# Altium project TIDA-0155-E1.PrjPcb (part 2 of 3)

## Sheet Page3.SchDoc
size 431 x 279 mm; Date: Not shown in title block; ApprovedBy: Not shown in title block; CheckedBy: Not shown in title block; Author: Not shown in title block; CompanyName: Not shown in title block; Engineer: Not shown in title block; Organization: Not shown in title block; Address1: Not shown in title block; Address2: Not shown in title block; Address3: Not shown in title block; Address4: Not shown in title block; DocumentNumber: 1; Revision: Use project parameter SCH_Rev; SheetNumber: 2; SheetTotal: 3; PageSetup: Record=PageOptions¦CenterHorizontal=True¦CenterVertical=True¦PrintScale=1.00¦XCorrection=1.00¦YCorrection=1.00¦PrintKind=0¦BorderSize=5000000¦LeftOffset=0¦BottomOffset=0¦Orientation=2¦PaperLength=1000¦PaperWidth=1000¦Scale=100¦PaperSource=15¦PrintQuality=600¦MediaType=1¦DitherType=10¦PaperKind=Letter¦PrintScaleMode=1
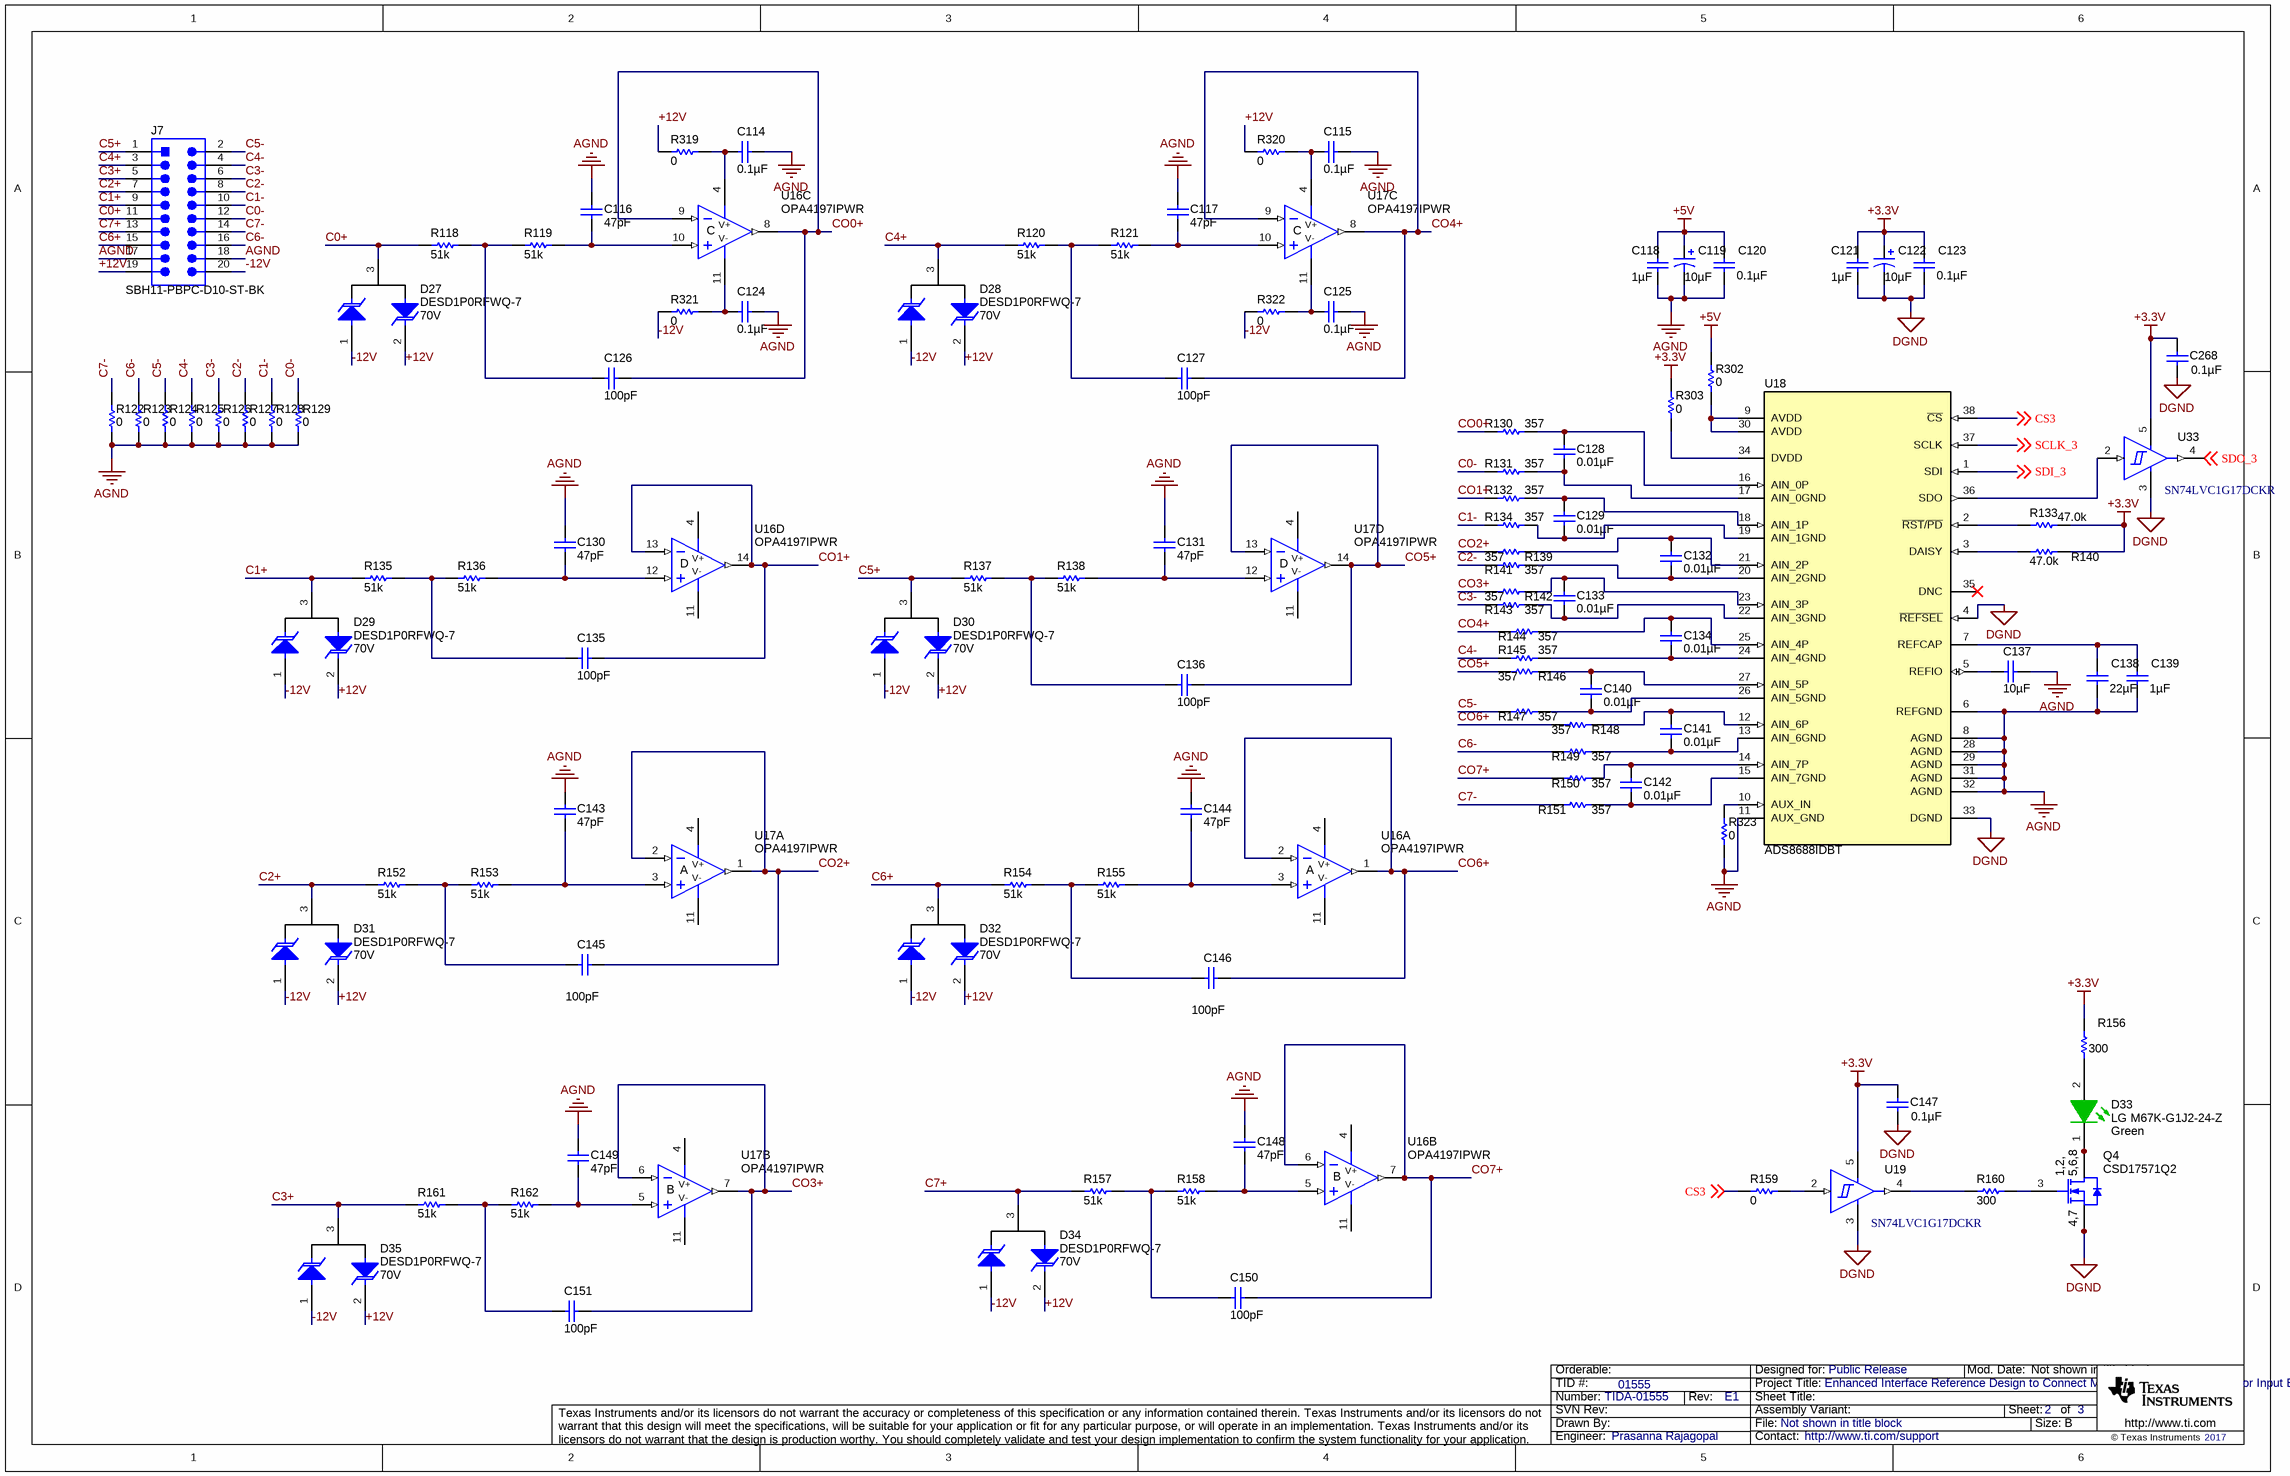
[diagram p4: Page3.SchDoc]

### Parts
C114  ValueDisplayed: 0.1µF  [0603]  (hidden comment: 06035C104KAT2A)
C115  ValueDisplayed: 0.1µF  [0603]  (hidden comment: 06035C104KAT2A)
C116  ValueDisplayed: 47pF  [0603]  (hidden comment: C0603C470J5GACTU)
C117  ValueDisplayed: 47pF  [0603]  (hidden comment: C0603C470J5GACTU)
C118  ValueDisplayed: 1µF  [0805_HV]  (hidden comment: LMK212B7105KD-T)
C119  ValueDisplayed: 10µF  [3216-18]  (hidden comment: TAJA106M010RNJ)
C120  ValueDisplayed: 0.1µF  [0402]  (hidden comment: C1005X5R1A104K050BA)
C121  ValueDisplayed: 1µF  [0805_HV]  (hidden comment: LMK212B7105KD-T)
C122  ValueDisplayed: 10µF  [3216-18]  (hidden comment: TAJA106M010RNJ)
C123  ValueDisplayed: 0.1µF  [0402]  (hidden comment: C1005X5R1A104K050BA)
C124  ValueDisplayed: 0.1µF  [0603]  (hidden comment: 06035C104KAT2A)
C125  ValueDisplayed: 0.1µF  [0603]  (hidden comment: 06035C104KAT2A)
C126  ValueDisplayed: 100pF  [0603]  (hidden comment: 06035A101FAT2A)
C127  ValueDisplayed: 100pF  [0603]  (hidden comment: 06035A101FAT2A)
C128  ValueDisplayed: 0.01µF  [0603]  (hidden comment: C1608X7R1H103K080AA)
C129  ValueDisplayed: 0.01µF  [0603]  (hidden comment: C1608X7R1H103K080AA)
C130  ValueDisplayed: 47pF  [0603]  (hidden comment: C0603C470J5GACTU)
C131  ValueDisplayed: 47pF  [0603]  (hidden comment: C0603C470J5GACTU)
C132  ValueDisplayed: 0.01µF  [0603]  (hidden comment: C1608X7R1H103K080AA)
C133  ValueDisplayed: 0.01µF  [0603]  (hidden comment: C1608X7R1H103K080AA)
C134  ValueDisplayed: 0.01µF  [0603]  (hidden comment: C1608X7R1H103K080AA)
C135  ValueDisplayed: 100pF  [0603]  (hidden comment: 06035A101FAT2A)
C136  ValueDisplayed: 100pF  [0603]  (hidden comment: 06035A101FAT2A)
C137  ValueDisplayed: 10µF  [0805_HV]  (hidden comment: GRM21BR71A106KE51L)
C138  ValueDisplayed: 22µF  [1210_280]  (hidden comment: C3225X7R1C226K250AC)
C139  ValueDisplayed: 1µF  [0603]  (hidden comment: C1608X7R1C105K080AC)
C140  ValueDisplayed: 0.01µF  [0603]  (hidden comment: C1608X7R1H103K080AA)
C141  ValueDisplayed: 0.01µF  [0603]  (hidden comment: C1608X7R1H103K080AA)
C142  ValueDisplayed: 0.01µF  [0603]  (hidden comment: C1608X7R1H103K080AA)
C143  ValueDisplayed: 47pF  [0603]  (hidden comment: C0603C470J5GACTU)
C144  ValueDisplayed: 47pF  [0603]  (hidden comment: C0603C470J5GACTU)
C145  ValueDisplayed: 100pF  [0603]  (hidden comment: 06035A101FAT2A)
C146  ValueDisplayed: 100pF  [0603]  (hidden comment: 06035A101FAT2A)
C147  ValueDisplayed: 0.1µF  [0603]  (hidden comment: GRM188R71C104KA01D)
C148  ValueDisplayed: 47pF  [0603]  (hidden comment: C0603C470J5GACTU)
C149  ValueDisplayed: 47pF  [0603]  (hidden comment: C0603C470J5GACTU)
C150  ValueDisplayed: 100pF  [0603]  (hidden comment: 06035A101FAT2A)
C151  ValueDisplayed: 100pF  [0603]  (hidden comment: 06035A101FAT2A)
C268  ValueDisplayed: 0.1µF  [0603]  (hidden comment: GRM188R71C104KA01D)
D27  DESD1P0RFWQ-7  value 70V  [SOT-323]
D28  DESD1P0RFWQ-7  value 70V  [SOT-323]
D29  DESD1P0RFWQ-7  value 70V  [SOT-323]
D30  DESD1P0RFWQ-7  value 70V  [SOT-323]
D31  DESD1P0RFWQ-7  value 70V  [SOT-323]
D32  DESD1P0RFWQ-7  value 70V  [SOT-323]
D33  LG M67K-G1J2-24-Z  value Green  [LG_M67K_Green]
D34  DESD1P0RFWQ-7  value 70V  [SOT-323]
D35  DESD1P0RFWQ-7  value 70V  [SOT-323]
J7  SBH11-PBPC-D10-ST-BK  [Sullins_SBH11-xxxC-D10-ST]
Q4  CSD17571Q2  [DQK0006C]
R118  ValueDisplayed: 51k  [0603]  (hidden comment: CRCW060351K0JNEA)
R119  ValueDisplayed: 51k  [0603]  (hidden comment: CRCW060351K0JNEA)
R120  ValueDisplayed: 51k  [0603]  (hidden comment: CRCW060351K0JNEA)
R121  ValueDisplayed: 51k  [0603]  (hidden comment: CRCW060351K0JNEA)
R122  ValueDisplayed: 0  [0603]  (hidden comment: CRCW06030000Z0EA)
R123  ValueDisplayed: 0  [0603]  (hidden comment: CRCW06030000Z0EA)
R124  ValueDisplayed: 0  [0603]  (hidden comment: CRCW06030000Z0EA)
R125  ValueDisplayed: 0  [0603]  (hidden comment: CRCW06030000Z0EA)
R126  ValueDisplayed: 0  [0603]  (hidden comment: CRCW06030000Z0EA)
R127  ValueDisplayed: 0  [0603]  (hidden comment: CRCW06030000Z0EA)
R128  ValueDisplayed: 0  [0603]  (hidden comment: CRCW06030000Z0EA)
R129  ValueDisplayed: 0  [0603]  (hidden comment: CRCW06030000Z0EA)
R130  ValueDisplayed: 357  [0402]  (hidden comment: CRCW0402357RFKED)
R131  ValueDisplayed: 357  [0402]  (hidden comment: CRCW0402357RFKED)
R132  ValueDisplayed: 357  [0402]  (hidden comment: CRCW0402357RFKED)
R133  ValueDisplayed: 47.0k  [0603]  (hidden comment: RC0603FR-0747KL)
R134  ValueDisplayed: 357  [0402]  (hidden comment: CRCW0402357RFKED)
R135  ValueDisplayed: 51k  [0603]  (hidden comment: CRCW060351K0JNEA)
R136  ValueDisplayed: 51k  [0603]  (hidden comment: CRCW060351K0JNEA)
R137  ValueDisplayed: 51k  [0603]  (hidden comment: CRCW060351K0JNEA)
R138  ValueDisplayed: 51k  [0603]  (hidden comment: CRCW060351K0JNEA)
R139  ValueDisplayed: 357  [0402]  (hidden comment: CRCW0402357RFKED)
R140  ValueDisplayed: 47.0k  [0603]  (hidden comment: RC0603FR-0747KL)
R141  ValueDisplayed: 357  [0402]  (hidden comment: CRCW0402357RFKED)
R142  ValueDisplayed: 357  [0402]  (hidden comment: CRCW0402357RFKED)
R143  ValueDisplayed: 357  [0402]  (hidden comment: CRCW0402357RFKED)
R144  ValueDisplayed: 357  [0402]  (hidden comment: CRCW0402357RFKED)
R145  ValueDisplayed: 357  [0402]  (hidden comment: CRCW0402357RFKED)
R146  ValueDisplayed: 357  [0402]  (hidden comment: CRCW0402357RFKED)
R147  ValueDisplayed: 357  [0402]  (hidden comment: CRCW0402357RFKED)
R148  ValueDisplayed: 357  [0402]  (hidden comment: CRCW0402357RFKED)
R149  ValueDisplayed: 357  [0402]  (hidden comment: CRCW0402357RFKED)
R150  ValueDisplayed: 357  [0402]  (hidden comment: CRCW0402357RFKED)
R151  ValueDisplayed: 357  [0402]  (hidden comment: CRCW0402357RFKED)
R152  ValueDisplayed: 51k  [0603]  (hidden comment: CRCW060351K0JNEA)
R153  ValueDisplayed: 51k  [0603]  (hidden comment: CRCW060351K0JNEA)
R154  ValueDisplayed: 51k  [0603]  (hidden comment: CRCW060351K0JNEA)
R155  ValueDisplayed: 51k  [0603]  (hidden comment: CRCW060351K0JNEA)
R156  ValueDisplayed: 300  [0603]  (hidden comment: CRCW0603300RJNEA)
R157  ValueDisplayed: 51k  [0603]  (hidden comment: CRCW060351K0JNEA)
R158  ValueDisplayed: 51k  [0603]  (hidden comment: CRCW060351K0JNEA)
R159  ValueDisplayed: 0  [0603]  (hidden comment: RMCF0603ZT0R00)
R160  ValueDisplayed: 300  [0603]  (hidden comment: CRCW0603300RJNEA)
R161  ValueDisplayed: 51k  [0603]  (hidden comment: CRCW060351K0JNEA)
R162  ValueDisplayed: 51k  [0603]  (hidden comment: CRCW060351K0JNEA)
R302  ValueDisplayed: 0  [0603]  (hidden comment: CRCW06030000Z0EA)
R303  ValueDisplayed: 0  [0603]  (hidden comment: CRCW06030000Z0EA)
R319  ValueDisplayed: 0  [0402]  (hidden comment: CRCW04020000Z0ED)
R320  ValueDisplayed: 0  [0402]  (hidden comment: CRCW04020000Z0ED)
R321  ValueDisplayed: 0  [0402]  (hidden comment: CRCW04020000Z0ED)
R322  ValueDisplayed: 0  [0402]  (hidden comment: CRCW04020000Z0ED)
R323  ValueDisplayed: 0  [0402]  (hidden comment: CRCW04020000Z0ED)
U16  OPA4197IPWR  [PW0014A_N]  (parts A,B,C,D of 4)
U17  OPA4197IPWR  [PW0014A_N]  (parts A,B,C,D of 4)
U18  ADS8688IDBT  [DBT0038A_N]
U19  SN74LVC1G17DCKR  [DCK0005A_N]
U33  SN74LVC1G17DCKR  [DCK0005A_N]

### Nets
+3.3V: C121.1 C122.1(+) C123.1 C147.1 C268.1 R133.2 R140.2 R156.2 R303.2 U19.5(VCC) U33.5(VCC)
+5V: C118.1 C119.1(+) C120.1 R302.2
+12V: D27.2(C) D28.2(C) D29.2(C) D30.2(C) D31.2(C) D32.2(C) D34.2(C) D35.2(C) J7.19 R319.1 R320.1
-12V: D27.1(A) D28.1(A) D29.1(A) D30.1(A) D31.1(A) D32.1(A) D34.1(A) D35.1(A) J7.20 R321.1 R322.1
AGND: C114.1 C115.1 C116.1 C117.1 C118.2 C119.2(-) C120.2 C124.1 C125.1 C130.1 C131.1 C137.2 C138.2 C139.2 C143.1 C144.1 C148.1 C149.1 J7.17 J7.18 R122.1 R123.1 R124.1 R125.1 R126.1 R127.1 R128.1 R129.1 R323.1 U18.6(REFGND) U18.8(AGND) U18.11(AUX_GND) U18.28(AGND) U18.29(AGND) U18.31(AGND) U18.32(AGND)
DGND: C121.2 C122.2(-) C123.2 C147.2 C268.2 Q4.4(S) Q4.7(S) U18.4(~{REFSEL}) U18.33(DGND) U19.3(GND) U33.3(GND)
C0+: D27.3(C) J7.11 R118.1
C0-: J7.12 R129.2 R131.1
C1+: D29.3(C) J7.9 R135.1
C1-: J7.10 R128.2 R134.1
C2+: D31.3(C) J7.7 R152.1
C2-: J7.8 R127.2 R141.1
C3+: D35.3(C) J7.5 R161.1
C3-: J7.6 R126.2 R143.1
C4+: D28.3(C) J7.3 R120.1
C4-: J7.4 R125.2 R145.1
C5+: D30.3(C) J7.1 R137.1
C5-: J7.2 R124.2 R147.1
C6+: D32.3(C) J7.15 R154.1
C6-: J7.16 R123.2 R149.1
C7+: D34.3(C) J7.13 R157.1
C7-: J7.14 R122.2 R151.1
CO0+: C126.1 R130.1 U16.8(OUT) U16.9(IN-)
CO1+: C135.1 R132.1 U16.13(IN-) U16.14(OUT)
CO2+: C145.1 R139.1 U17.1(OUT) U17.2(IN-)
CO3+: C151.1 R142.1 U17.6(IN-) U17.7(OUT)
CO4+: C127.1 R144.1 U17.8(OUT) U17.9(IN-)
CO5+: C136.1 R146.1 U17.13(IN-) U17.14(OUT)
CO6+: C146.1 R148.1 U16.1(OUT) U16.2(IN-)
CO7+: C150.1 R150.1 U16.6(IN-) U16.7(OUT)
CS3: R159.1 U18.38(~{CS}) ; off-sheet CS3
SCLK_3: U18.37(SCLK) ; off-sheet SCLK_3
SDI_3: U18.1(SDI) ; off-sheet SDI_3
SDO_3: U33.4(Y) ; off-sheet SDO_3
NetC114_2: C114.2 R319.2 U16.4(V+)
NetC115_2: C115.2 R320.2 U17.4(V+)
NetC116_2: C116.2 R119.2 U16.10(IN+)
NetC117_2: C117.2 R121.2 U17.10(IN+)
NetC124_2: C124.2 R321.2 U16.11(V-)
NetC125_2: C125.2 R322.2 U17.11(V-)
NetC126_2: C126.2 R118.2 R119.1
NetC127_2: C127.2 R120.2 R121.1
NetC128_1: C128.1 R130.2 U18.16(AIN_0P)
NetC128_2: C128.2 R131.2 U18.17(AIN_0GND)
NetC129_1: C129.1 R132.2 U18.18(AIN_1P)
NetC129_2: C129.2 R134.2 U18.19(AIN_1GND)
NetC130_2: C130.2 R136.2 U16.12(IN+)
NetC131_2: C131.2 R138.2 U17.12(IN+)
NetC132_1: C132.1 R139.2 U18.21(AIN_2P)
NetC132_2: C132.2 R141.2 U18.20(AIN_2GND)
NetC133_1: C133.1 R142.2 U18.23(AIN_3P)
NetC133_2: C133.2 R143.2 U18.22(AIN_3GND)
NetC134_1: C134.1 R144.2 U18.25(AIN_4P)
NetC134_2: C134.2 R145.2 U18.24(AIN_4GND)
NetC135_2: C135.2 R135.2 R136.1
NetC136_2: C136.2 R137.2 R138.1
NetC137_1: C137.1 U18.5(REFIO)
NetC138_1: C138.1 C139.1 U18.7(REFCAP)
NetC140_1: C140.1 R146.2 U18.27(AIN_5P)
NetC140_2: C140.2 R147.2 U18.26(AIN_5GND)
NetC141_1: C141.1 R148.2 U18.12(AIN_6P)
NetC141_2: C141.2 R149.2 U18.13(AIN_6GND)
NetC142_1: C142.1 R150.2 U18.14(AIN_7P)
NetC142_2: C142.2 R151.2 U18.15(AIN_7GND)
NetC143_2: C143.2 R153.2 U17.3(IN+)
NetC144_2: C144.2 R155.2 U16.3(IN+)
NetC145_2: C145.2 R152.2 R153.1
NetC146_2: C146.2 R154.2 R155.1
NetC148_2: C148.2 R158.2 U16.5(IN+)
NetC149_2: C149.2 R162.2 U17.5(IN+)
NetC150_2: C150.2 R157.2 R158.1
NetC151_2: C151.2 R161.2 R162.1
NetD33_1: D33.1(K) Q4.1(D) Q4.2(D) Q4.5(D) Q4.6(D) Q4.8(D)
NetD33_2: D33.2(A) R156.1
NetQ4_3: Q4.3(G) R160.1
NetR133_1: R133.1 U18.2(~{RST}/~{PD})
NetR140_1: R140.1 U18.3(DAISY)
NetR159_2: R159.2 U19.2(A)
NetR160_2: R160.2 U19.4(Y)
NetR302_1: R302.1 U18.9(AVDD) U18.30(AVDD)
NetR303_1: R303.1 U18.34(DVDD)
NetR323_2: R323.2 U18.10(AUX_IN)
NetU18_36: U18.36(SDO) U33.2(A)

Not connected (* = marked no-connect by the designer): U18 35(DNC)*

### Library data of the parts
C114 C115 C124 C125 = 06035C104KAT2A: CAP, CERM, 0.1 µF, 50 V,+/- 10%, X7R, 0603; Manufacturer: AVX; Polarized: N; CompType: Capacitor; Value: 0.1uF; U/M: EA; Cap_F: 0.0000001; Tolerance_%: 10; VDC_V: 50; Value2: 50V; TaMin_C: -55; TaMax_C: 125; SizeArea_mm2: 1.28; SizeAreaWB_mm2: 4.68; SizeX_mm: 1.6; SizeY_mm: 0.8; SizeZ_mm: 1; AEC Category: Q200; Green_Lifecycle: Active; Green_REACh: Passed
C116 C117 C130 C131 C143 C144 C148 C149 = C0603C470J5GACTU: CAP, CERM, 47 pF, 50 V,+/- 5%, C0G/NP0, 0603; Manufacturer: Kemet; Polarized: N; CompType: Capacitor; Value: 47pF; U/M: EA; Cap_F: 0.000000000047; Tolerance_%: 5; VDC_V: 50; Value2: 50V; TaMin_C: -55; TaMax_C: 125; SizeArea_mm2: 1.28; SizeAreaWB_mm2: 4.68; SizeX_mm: 1.6; SizeY_mm: 0.8; SizeZ_mm: 1; AEC Category: Q200; Green_Lifecycle: Active; Green_REACh: Passed
C118 C121 = LMK212B7105KD-T: CAP, CERM, 1 µF, 10 V, +/- 10%, X7R, 0805; Manufacturer: Taiyo Yuden; Polarized: N; CompType: Capacitor; Value: 1uF; U/M: EA; Cap_F: 0.000001; Tolerance_%: 10; Value1: Unknown; Value2: 10V; TaMin_C: -55; TaMax_C: 125; Cap_Case: 0805; SizeArea_mm2: 2.5; SizeAreaWB_mm2: 6.75; SizeX_mm: 2; SizeY_mm: 1.25; SizeZ_mm: 1.45; AEC Category: Q200
C119 C122 = TAJA106M010RNJ: CAP, TA, 10 µF, 10 V, +/- 20%, 3 ohm, SMD; Manufacturer: AVX; Polarized: Y; CompType: Capacitor; Value: 10uF; U/M: EA; Cap_F: 0.00001; Tolerance_%: 20; Value1: 3 ohm; VDC_V: 10; Value2: 10V; ESR_ohm: 3; TaMin_C: -55; TaMax_C: 125; SizeAreaWB_mm2: 10.92; SizeArea_mm2: 5.12; SizeX_mm: 3.2; SizeY_mm: 1.6; SizeZ_mm: 1.8; AEC Category: Q200
C120 C123 = C1005X5R1A104K050BA: CAP, CERM, 0.1 µF, 10 V, +/- 10%, X5R, 0402; Manufacturer: TDK; Polarized: N; CompType: Capacitor; Value: 0.1uF; U/M: EA; Cap_F: 0.0000001; Tolerance_%: 10; Value1: Unknown; Value2: 10V; TaMin_C: -55; TaMax_C: 85; SizeArea_mm2: 0.5; SizeAreaWB_mm2: 3; SizeX_mm: 1; SizeZ_mm: 0.6; AEC Category: Q200
C126 C127 C135 C136 C145 C146 C150 C151 = 06035A101FAT2A: CAP, CERM, 100 pF, 50 V,+/- 1%, C0G/NP0, 0603; Manufacturer: AVX; Polarized: N; CompType: Capacitor; Value: 100pF; U/M: EA; Cap_F: 0.0000000001; Tolerance_%: 1; VDC_V: 50; Value2: 50V; TaMin_C: -55; TaMax_C: 125; SizeArea_mm2: 1.28; SizeAreaWB_mm2: 4.68; SizeX_mm: 1.6; SizeY_mm: 0.8; AEC Category: Q200; Green_Lifecycle: Active; Green_REACh: Passed
C128 C129 C132-C134 C140-C142 = C1608X7R1H103K080AA: CAP, CERM, 0.01 µF, 50 V,+/- 10%, X7R, 0603; Manufacturer: TDK; Polarized: N; CompType: Capacitor; Value: 0.01uF; U/M: EA; Cap_F: 0.00000001; Tolerance_%: 10; ESR_ohm: 0.0539; Value1: 0.0539 ohm; VDC_V: 50; Value2: 50V; TaMin_C: -55; TaMax_C: 125; SizeArea_mm2: 1.28; SizeAreaWB_mm2: 4.68; SizeX_mm: 1.6; SizeY_mm: 0.8; SizeZ_mm: 1; AEC Category: Q200; Green_Lifecycle: NRND; Green_REACh: Passed
C137 = GRM21BR71A106KE51L: CAP, CERM, 10 µF, 10 V,+/- 10%, X7R, 0805; Manufacturer: MuRata; Polarized: N; CompType: Capacitor; Value: 10uF; U/M: EA; Cap_F: 0.00001; Tolerance_%: 10; ESR_ohm: 0.003; Value1: 0.003 ohm; Value2: 10V; TaMin_C: -55; TaMax_C: 125; Cap_Case: 0805; SizeArea_mm2: 2.5; SizeAreaWB_mm2: 6.75; SizeX_mm: 2; SizeY_mm: 1.25; SizeZ_mm: 1.45; AEC Category: Q200; Green_Lifecycle: Active; Green_REACh: Passed
C138 = C3225X7R1C226K250AC: CAP, CERM, 22 µF, 16 V,+/- 10%, X7R, 1210; Manufacturer: TDK; Polarized: N; CompType: Capacitor; Value: 22uF; U/M: EA; Cap_F: 0.000022; Tolerance_%: 10; ESR_ohm: 0.002582; Value1: 0.002582 ohm; VDC_V: 16; Value2: 16V; IRMS_A: 4.57562; TaMin_C: -55; TaMax_C: 125; Cap_Case: 1210; SizeArea_mm2: 8; SizeAreaWB_mm2: 14.7; SizeX_mm: 3.2; SizeY_mm: 2.5; SizeZ_mm: 2.8; AEC Category: Q200; Green_Lifecycle: Active; Green_REACh: Passed
C139 = C1608X7R1C105K080AC: CAP, CERM, 1 µF, 16 V,+/- 10%, X7R, 0603; Manufacturer: TDK; Polarized: N; CompType: Capacitor; Value: 1uF; U/M: EA; Cap_F: 0.000001; Tolerance_%: 10; ESR_ohm: 0.0057; Value1: 0.0057 ohm; VDC_V: 16; Value2: 16V; TaMin_C: -55; TaMax_C: 125; SizeArea_mm2: 1.28; SizeAreaWB_mm2: 4.68; SizeX_mm: 1.6; SizeY_mm: 0.8; SizeZ_mm: 1; AEC Category: Q200; Green_Lifecycle: Active; Green_REACh: Passed
C147 C268 = GRM188R71C104KA01D: CAP, CERM, 0.1 µF, 16 V, +/- 10%, X7R, 0603; Manufacturer: MuRata; Polarized: N; CompType: Capacitor; Value: 0.1uF; U/M: EA; Cap_F: 0.0000001; Tolerance_%: 10; Value1: Unknown; VDC_V: 16; Value2: 16V; TaMin_C: -55; TaMax_C: 125; SizeArea_mm2: 1.28; SizeAreaWB_mm2: 4.68; SizeX_mm: 1.6; SizeY_mm: 0.8; SizeZ_mm: 1; AEC Category: Q200
D27-D32 D34 D35 = DESD1P0RFWQ-7: Diode, TVS, Uni, 70 V, SOT-323; Manufacturer: Diodes Inc.; SymbolCreator: x0208325; U/M: EA; Power_W: 0.2; Vr_V: 70; Value1: 0.2W; SizeAreaWB_mm2: 10.24; SizeArea_mm2: 4.84; SizeX_mm: 2.2; SizeZ_mm: 1.1; AEC Category: Q101
D33 = LG M67K-G1J2-24-Z: LED, Green, SMD; Manufacturer: OSRAM; SymbolCreator: Altium; Type: AlInGaP; Vf_V: 1.8; Value2: 1.8V; Io_A: 0.002; Vr_V: 12; Tjmax_C: 125; Value1: W; Angle: 120; U/M: EA
J7 = SBH11-PBPC-D10-ST-BK: Header (Shrouded), 2.54mm, 10x2, Gold, Black, TH; Manufacturer: Sullins Connector Solutions; SymbolCreator: a0412235; Pitch_mm: 2.54; Gender: Male; Shrouded: Y; Row_Count: 2; Current_A: 3; Voltage_V: 1000; Green_Lifecycle: Not Set; Green_REACh: Incomplete
Q4 = CSD17571Q2: MOSFET, N-CH, 30 V, 22 A, DQK0006C (WSON-6); Manufacturer: Texas Instruments; Alternate Manufacturer: None; U/M: EA; ChType: N; Value: 30V; VdsMax_V: 30; Value1: 0.029 ohm; Rdson45_ohm: 0.029; Value2: 2.4 nC; QgTyp_nC: 2.4; Vgs_V: 20; IdsMax_A: 22; SizeAreaWB_mm2: 9; SizeArea_mm2: 4; SizeX_mm: 2; SizeZ_mm: 0.8; AEC Category: Q101
R118-R121 R135-R138 R152-R155 R157 R158 R161 R162 = CRCW060351K0JNEA: RES, 51 k, 5%, 0.1 W, 0603; Manufacturer: Vishay-Dale; CompType: Resistor; Value: 51k; Res_ohm: 51000; Value_Code: 51k0; Tolerance_%: 5; Power_W: 0.1; Value2: 0.1W; VDC_V: 75; TempCo: 200 ppm/C; SizeArea_mm2: 1.28; SizeX_mm: 1.6; SizeY_mm: 0.8; SizeZ_mm: 1; EIA_Code: E24; U/M: EA; AEC Category: Q200; Green_Lifecycle: Active; Green_REACh: Passed
R122-R129 R302 R303 = CRCW06030000Z0EA: RES, 0, 5%, 0.1 W, 0603; Manufacturer: Vishay-Dale; CompType: Resistor; Value: 0; Value_Code: 0000; Tolerance_%: 5; Power_W: 0.1; Value2: 0.1W; VDC_V: 75; TempCo: 200 ppm/C; EIA_Code: E24; U/M: EA
R130-R132 R134 R139 R141-R151 = CRCW0402357RFKED: RES, 357, 1%, 0.063 W, 0402; Manufacturer: Vishay-Dale; CompType: Resistor; Value: 357; Value_Code: 357R; Tolerance_%: 1; Power_W: 0.063; Value2: 0.063W; VDC_V: 50; TempCo: 100 ppm/C; SizeArea_mm2: 0.5; SizeZ_mm: 0.6; EIA_Code: E96; U/M: EA; AEC Category: Q200; Green_Lifecycle: Active; Green_REACh: Passed
R133 R140 = RC0603FR-0747KL: RES, 47.0 k, 1%, 0.1 W, 0603; Manufacturer: Yageo America; CompType: Resistor; Value: 47.0k; Res_ohm: 47000; Value_Code: 47k0; Tolerance_%: 1; Power_W: 0.1; Value2: 0.1W; VDC_V: 150; TempCo: 200 ppm/C; SizeArea_mm2: 1.28; SizeX_mm: 1.6; SizeY_mm: 0.8; U/M: EA; AEC Category: Q200; Green_Lifecycle: Active; Green_REACh: Passed
R156 R160 = CRCW0603300RJNEA: RES, 300, 5%, 0.1 W, 0603; Manufacturer: Vishay-Dale; CompType: Resistor; Value: 300; Value_Code: 300R; Tolerance_%: 5; Power_W: 0.1; Value2: 0.1W; VDC_V: 75; TempCo: 200 ppm/C; SizeArea_mm2: 1.28; SizeX_mm: 1.6; SizeY_mm: 0.8; SizeZ_mm: 1; EIA_Code: E24; U/M: EA; AEC Category: Q200
R159 = RMCF0603ZT0R00: RES, 0, 1%, 0.1 W, AEC-Q200 Grade 0, 0603; Manufacturer: Stackpole Electronics Inc; CompType: Resistor; Value: 0; Tolerance_%: 1; Power_W: 0.1; Value2: 0.1W; TempCo: ppm/C; SizeArea_mm2: 1.28; SizeX_mm: 1.6; SizeY_mm: 0.8; U/M: EA; AEC Category: Q200; AEC Qualified: Y
R319-R323 = CRCW04020000Z0ED: RES, 0, 5%, 0.063 W, 0402; Manufacturer: Vishay-Dale; CompType: Resistor; Value: 0; Value_Code: 0000; Tolerance_%: 5; Power_W: 0.063; Value2: 0.063W; VDC_V: 50; TempCo: 200 ppm/C; EIA_Code: E24; U/M: EA; SizeArea_mm2: 0.5; SizeX_mm: 1; SizeZ_mm: 0.6; AEC Category: Q200; Green_Lifecycle: Active; Green_REACh: Passed
U16 U17 = OPA4197IPWR: 36-V, Precision, Rail-to-Rail Input Output, Low Offset Voltage Op Amp, PW0014A (TSSOP-14); Manufacturer: Texas Instruments; SymbolCreator: a0412235; SizeArea_mm2: 32; SizeAreaWB_mm2: 58.8; SizeX_mm: 6.4; SizeY_mm: 5; SizeZ_mm: 1.2; CompType: IC; U/M: EA
U18 = ADS8688IDBT: 16-Bit, 500-kSPS, 8-Channel, Single-Supply, SAR ADCs with Bipolar Input Ranges, DBT0038A (TSSOP-38); Manufacturer: Texas Instruments; SymbolCreator: Altium; SizeArea_mm2: 62.08; SizeAreaWB_mm2: 98.28; SizeX_mm: 6.4; SizeY_mm: 9.7; SizeZ_mm: 1.2; CompType: IC; U/M: EA
U19 U33 = SN74LVC1G17DCKR: SINGLE SCHMITT-TRIGGER BUFFER, DCK0005A (SOT-SC70-5); Alternate PartNumber: SN74LVC1G17DCKT; Manufacturer: Texas Instruments; SymbolCreator: a0799628; SizeArea_mm2: 4.2; SizeAreaWB_mm2: 9.3; SizeX_mm: 2.1; SizeY_mm: 2; SizeZ_mm: 1.1; CompType: IC; U/M: EA

## Sheet Page4.SchDoc
size 431 x 279 mm; Date: Not shown in title block; ApprovedBy: Not shown in title block; CheckedBy: Not shown in title block; Author: Not shown in title block; CompanyName: Not shown in title block; Engineer: Not shown in title block; Organization: Not shown in title block; Address1: Not shown in title block; Address2: Not shown in title block; Address3: Not shown in title block; Address4: Not shown in title block; DocumentNumber: 1; Revision: Use project parameter SCH_Rev; SheetNumber: 2; SheetTotal: 3; PageSetup: Record=PageOptions¦CenterHorizontal=True¦CenterVertical=True¦PrintScale=1.00¦XCorrection=1.00¦YCorrection=1.00¦PrintKind=0¦BorderSize=5000000¦LeftOffset=0¦BottomOffset=0¦Orientation=2¦PaperLength=1000¦PaperWidth=1000¦Scale=100¦PaperSource=15¦PrintQuality=600¦MediaType=1¦DitherType=10¦PaperKind=Letter¦PrintScaleMode=1
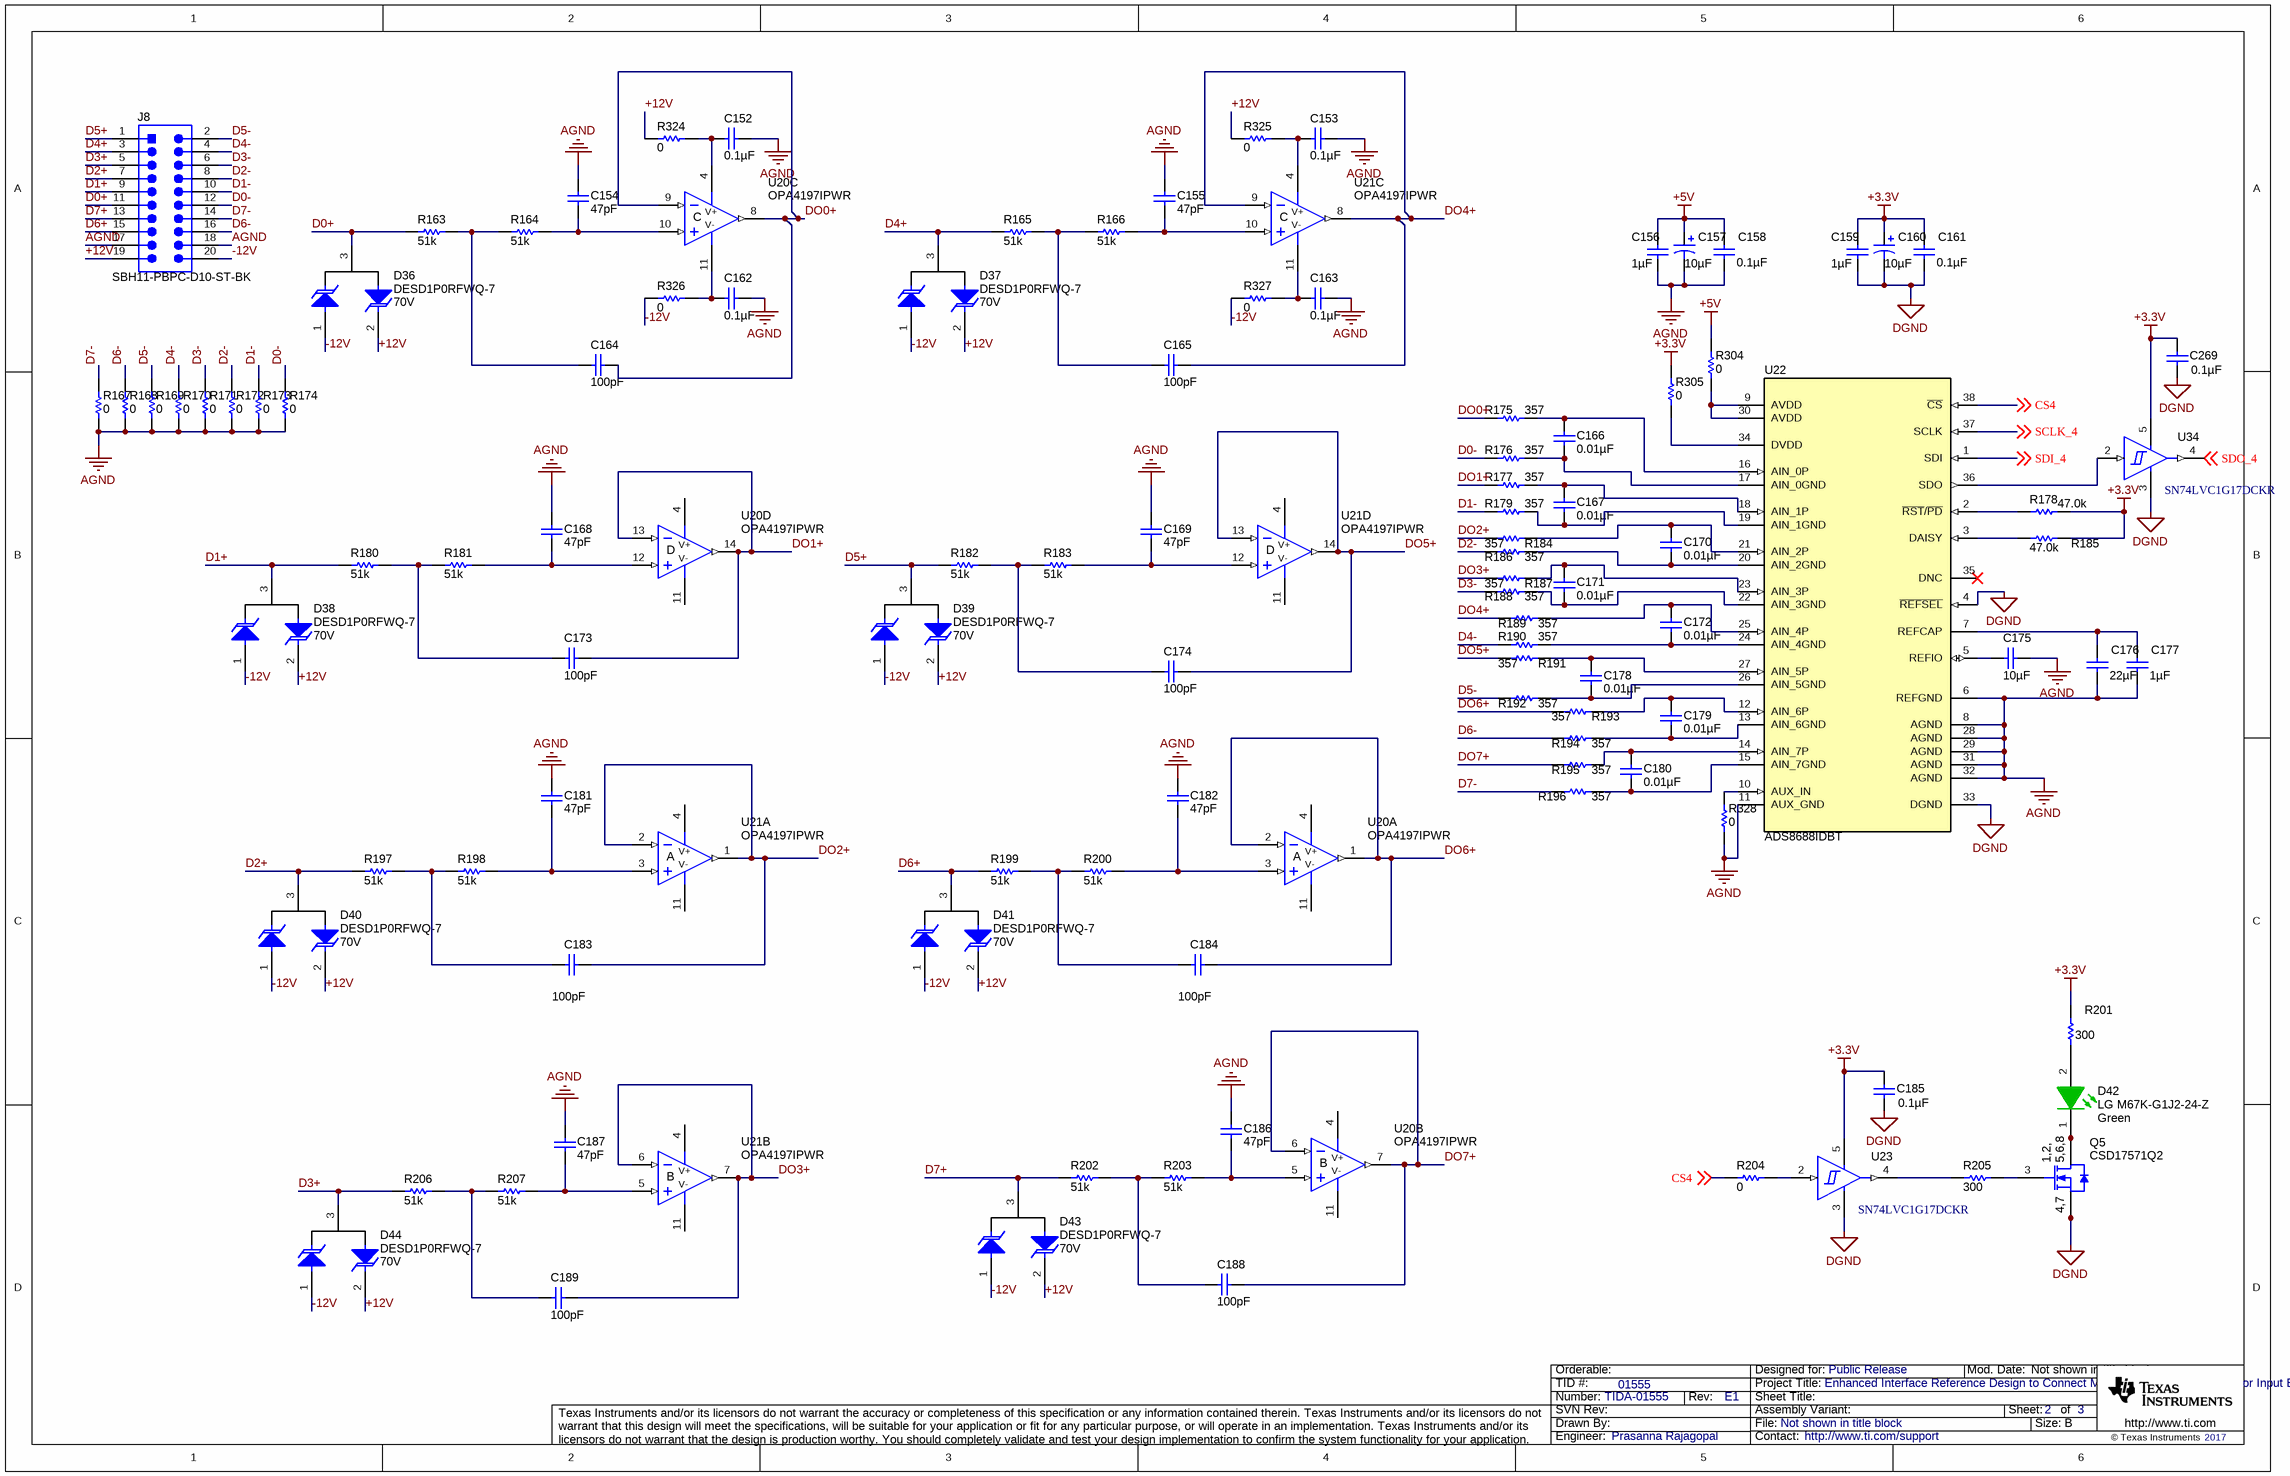
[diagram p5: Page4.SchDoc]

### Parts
C152  ValueDisplayed: 0.1µF  [0603]  (hidden comment: 06035C104KAT2A)
C153  ValueDisplayed: 0.1µF  [0603]  (hidden comment: 06035C104KAT2A)
C154  ValueDisplayed: 47pF  [0603]  (hidden comment: C0603C470J5GACTU)
C155  ValueDisplayed: 47pF  [0603]  (hidden comment: C0603C470J5GACTU)
C156  ValueDisplayed: 1µF  [0805_HV]  (hidden comment: LMK212B7105KD-T)
C157  ValueDisplayed: 10µF  [3216-18]  (hidden comment: TAJA106M010RNJ)
C158  ValueDisplayed: 0.1µF  [0402]  (hidden comment: C1005X5R1A104K050BA)
C159  ValueDisplayed: 1µF  [0805_HV]  (hidden comment: LMK212B7105KD-T)
C160  ValueDisplayed: 10µF  [3216-18]  (hidden comment: TAJA106M010RNJ)
C161  ValueDisplayed: 0.1µF  [0402]  (hidden comment: C1005X5R1A104K050BA)
C162  ValueDisplayed: 0.1µF  [0603]  (hidden comment: 06035C104KAT2A)
C163  ValueDisplayed: 0.1µF  [0603]  (hidden comment: 06035C104KAT2A)
C164  ValueDisplayed: 100pF  [0603]  (hidden comment: 06035A101FAT2A)
C165  ValueDisplayed: 100pF  [0603]  (hidden comment: 06035A101FAT2A)
C166  ValueDisplayed: 0.01µF  [0603]  (hidden comment: C1608X7R1H103K080AA)
C167  ValueDisplayed: 0.01µF  [0603]  (hidden comment: C1608X7R1H103K080AA)
C168  ValueDisplayed: 47pF  [0603]  (hidden comment: C0603C470J5GACTU)
C169  ValueDisplayed: 47pF  [0603]  (hidden comment: C0603C470J5GACTU)
C170  ValueDisplayed: 0.01µF  [0603]  (hidden comment: C1608X7R1H103K080AA)
C171  ValueDisplayed: 0.01µF  [0603]  (hidden comment: C1608X7R1H103K080AA)
C172  ValueDisplayed: 0.01µF  [0603]  (hidden comment: C1608X7R1H103K080AA)
C173  ValueDisplayed: 100pF  [0603]  (hidden comment: 06035A101FAT2A)
C174  ValueDisplayed: 100pF  [0603]  (hidden comment: 06035A101FAT2A)
C175  ValueDisplayed: 10µF  [0805_HV]  (hidden comment: GRM21BR71A106KE51L)
C176  ValueDisplayed: 22µF  [1210_280]  (hidden comment: C3225X7R1C226K250AC)
C177  ValueDisplayed: 1µF  [0603]  (hidden comment: C1608X7R1C105K080AC)
C178  ValueDisplayed: 0.01µF  [0603]  (hidden comment: C1608X7R1H103K080AA)
C179  ValueDisplayed: 0.01µF  [0603]  (hidden comment: C1608X7R1H103K080AA)
C180  ValueDisplayed: 0.01µF  [0603]  (hidden comment: C1608X7R1H103K080AA)
C181  ValueDisplayed: 47pF  [0603]  (hidden comment: C0603C470J5GACTU)
C182  ValueDisplayed: 47pF  [0603]  (hidden comment: C0603C470J5GACTU)
C183  ValueDisplayed: 100pF  [0603]  (hidden comment: 06035A101FAT2A)
C184  ValueDisplayed: 100pF  [0603]  (hidden comment: 06035A101FAT2A)
C185  ValueDisplayed: 0.1µF  [0603]  (hidden comment: GRM188R71C104KA01D)
C186  ValueDisplayed: 47pF  [0603]  (hidden comment: C0603C470J5GACTU)
C187  ValueDisplayed: 47pF  [0603]  (hidden comment: C0603C470J5GACTU)
C188  ValueDisplayed: 100pF  [0603]  (hidden comment: 06035A101FAT2A)
C189  ValueDisplayed: 100pF  [0603]  (hidden comment: 06035A101FAT2A)
C269  ValueDisplayed: 0.1µF  [0603]  (hidden comment: GRM188R71C104KA01D)
D36  DESD1P0RFWQ-7  value 70V  [SOT-323]
D37  DESD1P0RFWQ-7  value 70V  [SOT-323]
D38  DESD1P0RFWQ-7  value 70V  [SOT-323]
D39  DESD1P0RFWQ-7  value 70V  [SOT-323]
D40  DESD1P0RFWQ-7  value 70V  [SOT-323]
D41  DESD1P0RFWQ-7  value 70V  [SOT-323]
D42  LG M67K-G1J2-24-Z  value Green  [LG_M67K_Green]
D43  DESD1P0RFWQ-7  value 70V  [SOT-323]
D44  DESD1P0RFWQ-7  value 70V  [SOT-323]
J8  SBH11-PBPC-D10-ST-BK  [Sullins_SBH11-xxxC-D10-ST]
Q5  CSD17571Q2  [DQK0006C]
R163  ValueDisplayed: 51k  [0603]  (hidden comment: CRCW060351K0JNEA)
R164  ValueDisplayed: 51k  [0603]  (hidden comment: CRCW060351K0JNEA)
R165  ValueDisplayed: 51k  [0603]  (hidden comment: CRCW060351K0JNEA)
R166  ValueDisplayed: 51k  [0603]  (hidden comment: CRCW060351K0JNEA)
R167  ValueDisplayed: 0  [0603]  (hidden comment: CRCW06030000Z0EA)
R168  ValueDisplayed: 0  [0603]  (hidden comment: CRCW06030000Z0EA)
R169  ValueDisplayed: 0  [0603]  (hidden comment: CRCW06030000Z0EA)
R170  ValueDisplayed: 0  [0603]  (hidden comment: CRCW06030000Z0EA)
R171  ValueDisplayed: 0  [0603]  (hidden comment: CRCW06030000Z0EA)
R172  ValueDisplayed: 0  [0603]  (hidden comment: CRCW06030000Z0EA)
R173  ValueDisplayed: 0  [0603]  (hidden comment: CRCW06030000Z0EA)
R174  ValueDisplayed: 0  [0603]  (hidden comment: CRCW06030000Z0EA)
R175  ValueDisplayed: 357  [0402]  (hidden comment: CRCW0402357RFKED)
R176  ValueDisplayed: 357  [0402]  (hidden comment: CRCW0402357RFKED)
R177  ValueDisplayed: 357  [0402]  (hidden comment: CRCW0402357RFKED)
R178  ValueDisplayed: 47.0k  [0603]  (hidden comment: RC0603FR-0747KL)
R179  ValueDisplayed: 357  [0402]  (hidden comment: CRCW0402357RFKED)
R180  ValueDisplayed: 51k  [0603]  (hidden comment: CRCW060351K0JNEA)
R181  ValueDisplayed: 51k  [0603]  (hidden comment: CRCW060351K0JNEA)
R182  ValueDisplayed: 51k  [0603]  (hidden comment: CRCW060351K0JNEA)
R183  ValueDisplayed: 51k  [0603]  (hidden comment: CRCW060351K0JNEA)
R184  ValueDisplayed: 357  [0402]  (hidden comment: CRCW0402357RFKED)
R185  ValueDisplayed: 47.0k  [0603]  (hidden comment: RC0603FR-0747KL)
R186  ValueDisplayed: 357  [0402]  (hidden comment: CRCW0402357RFKED)
R187  ValueDisplayed: 357  [0402]  (hidden comment: CRCW0402357RFKED)
R188  ValueDisplayed: 357  [0402]  (hidden comment: CRCW0402357RFKED)
R189  ValueDisplayed: 357  [0402]  (hidden comment: CRCW0402357RFKED)
R190  ValueDisplayed: 357  [0402]  (hidden comment: CRCW0402357RFKED)
R191  ValueDisplayed: 357  [0402]  (hidden comment: CRCW0402357RFKED)
R192  ValueDisplayed: 357  [0402]  (hidden comment: CRCW0402357RFKED)
R193  ValueDisplayed: 357  [0402]  (hidden comment: CRCW0402357RFKED)
R194  ValueDisplayed: 357  [0402]  (hidden comment: CRCW0402357RFKED)
R195  ValueDisplayed: 357  [0402]  (hidden comment: CRCW0402357RFKED)
R196  ValueDisplayed: 357  [0402]  (hidden comment: CRCW0402357RFKED)
R197  ValueDisplayed: 51k  [0603]  (hidden comment: CRCW060351K0JNEA)
R198  ValueDisplayed: 51k  [0603]  (hidden comment: CRCW060351K0JNEA)
R199  ValueDisplayed: 51k  [0603]  (hidden comment: CRCW060351K0JNEA)
R200  ValueDisplayed: 51k  [0603]  (hidden comment: CRCW060351K0JNEA)
R201  ValueDisplayed: 300  [0603]  (hidden comment: CRCW0603300RJNEA)
R202  ValueDisplayed: 51k  [0603]  (hidden comment: CRCW060351K0JNEA)
R203  ValueDisplayed: 51k  [0603]  (hidden comment: CRCW060351K0JNEA)
R204  ValueDisplayed: 0  [0603]  (hidden comment: RMCF0603ZT0R00)
R205  ValueDisplayed: 300  [0603]  (hidden comment: CRCW0603300RJNEA)
R206  ValueDisplayed: 51k  [0603]  (hidden comment: CRCW060351K0JNEA)
R207  ValueDisplayed: 51k  [0603]  (hidden comment: CRCW060351K0JNEA)
R304  ValueDisplayed: 0  [0603]  (hidden comment: CRCW06030000Z0EA)
R305  ValueDisplayed: 0  [0603]  (hidden comment: CRCW06030000Z0EA)
R324  ValueDisplayed: 0  [0402]  (hidden comment: CRCW04020000Z0ED)
R325  ValueDisplayed: 0  [0402]  (hidden comment: CRCW04020000Z0ED)
R326  ValueDisplayed: 0  [0402]  (hidden comment: CRCW04020000Z0ED)
R327  ValueDisplayed: 0  [0402]  (hidden comment: CRCW04020000Z0ED)
R328  ValueDisplayed: 0  [0402]  (hidden comment: CRCW04020000Z0ED)
U20  OPA4197IPWR  [PW0014A_N]  (parts A,B,C,D of 4)
U21  OPA4197IPWR  [PW0014A_N]  (parts A,B,C,D of 4)
U22  ADS8688IDBT  [DBT0038A_N]
U23  SN74LVC1G17DCKR  [DCK0005A_N]
U34  SN74LVC1G17DCKR  [DCK0005A_N]

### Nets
+3.3V: C159.1 C160.1(+) C161.1 C185.1 C269.1 R178.2 R185.2 R201.2 R305.2 U23.5(VCC) U34.5(VCC)
+5V: C156.1 C157.1(+) C158.1 R304.2
+12V: D36.2(C) D37.2(C) D38.2(C) D39.2(C) D40.2(C) D41.2(C) D43.2(C) D44.2(C) J8.19 R324.1 R325.1
-12V: D36.1(A) D37.1(A) D38.1(A) D39.1(A) D40.1(A) D41.1(A) D43.1(A) D44.1(A) J8.20 R326.1 R327.1
AGND: C152.1 C153.1 C154.1 C155.1 C156.2 C157.2(-) C158.2 C162.1 C163.1 C168.1 C169.1 C175.2 C176.2 C177.2 C181.1 C182.1 C186.1 C187.1 J8.17 J8.18 R167.1 R168.1 R169.1 R170.1 R171.1 R172.1 R173.1 R174.1 R328.1 U22.6(REFGND) U22.8(AGND) U22.11(AUX_GND) U22.28(AGND) U22.29(AGND) U22.31(AGND) U22.32(AGND)
DGND: C159.2 C160.2(-) C161.2 C185.2 C269.2 Q5.4(S) Q5.7(S) U22.4(~{REFSEL}) U22.33(DGND) U23.3(GND) U34.3(GND)
CS4: R204.1 U22.38(~{CS}) ; off-sheet CS4
D0+: D36.3(C) J8.11 R163.1
D0-: J8.12 R174.2 R176.1
D1+: D38.3(C) J8.9 R180.1
D1-: J8.10 R173.2 R179.1
D2+: D40.3(C) J8.7 R197.1
D2-: J8.8 R172.2 R186.1
D3+: D44.3(C) J8.5 R206.1
D3-: J8.6 R171.2 R188.1
D4+: D37.3(C) J8.3 R165.1
D4-: J8.4 R170.2 R190.1
D5+: D39.3(C) J8.1 R182.1
D5-: J8.2 R169.2 R192.1
D6+: D41.3(C) J8.15 R199.1
D6-: J8.16 R168.2 R194.1
D7+: D43.3(C) J8.13 R202.1
D7-: J8.14 R167.2 R196.1
DO0+: C164.1 R175.1 U20.8(OUT) U20.9(IN-)
DO1+: C173.1 R177.1 U20.13(IN-) U20.14(OUT)
DO2+: C183.1 R184.1 U21.1(OUT) U21.2(IN-)
DO3+: C189.1 R187.1 U21.6(IN-) U21.7(OUT)
DO4+: C165.1 R189.1 U21.8(OUT) U21.9(IN-)
DO5+: C174.1 R191.1 U21.13(IN-) U21.14(OUT)
DO6+: C184.1 R193.1 U20.1(OUT) U20.2(IN-)
DO7+: C188.1 R195.1 U20.6(IN-) U20.7(OUT)
SCLK_4: U22.37(SCLK) ; off-sheet SCLK_4
SDI_4: U22.1(SDI) ; off-sheet SDI_4
SDO_4: U34.4(Y) ; off-sheet SDO_4
NetC152_2: C152.2 R324.2 U20.4(V+)
NetC153_2: C153.2 R325.2 U21.4(V+)
NetC154_2: C154.2 R164.2 U20.10(IN+)
NetC155_2: C155.2 R166.2 U21.10(IN+)
NetC162_2: C162.2 R326.2 U20.11(V-)
NetC163_2: C163.2 R327.2 U21.11(V-)
NetC164_2: C164.2 R163.2 R164.1
NetC165_2: C165.2 R165.2 R166.1
NetC166_1: C166.1 R175.2 U22.16(AIN_0P)
NetC166_2: C166.2 R176.2 U22.17(AIN_0GND)
NetC167_1: C167.1 R177.2 U22.18(AIN_1P)
NetC167_2: C167.2 R179.2 U22.19(AIN_1GND)
NetC168_2: C168.2 R181.2 U20.12(IN+)
NetC169_2: C169.2 R183.2 U21.12(IN+)
NetC170_1: C170.1 R184.2 U22.21(AIN_2P)
NetC170_2: C170.2 R186.2 U22.20(AIN_2GND)
NetC171_1: C171.1 R187.2 U22.23(AIN_3P)
NetC171_2: C171.2 R188.2 U22.22(AIN_3GND)
NetC172_1: C172.1 R189.2 U22.25(AIN_4P)
NetC172_2: C172.2 R190.2 U22.24(AIN_4GND)
NetC173_2: C173.2 R180.2 R181.1
NetC174_2: C174.2 R182.2 R183.1
NetC175_1: C175.1 U22.5(REFIO)
NetC176_1: C176.1 C177.1 U22.7(REFCAP)
NetC178_1: C178.1 R191.2 U22.27(AIN_5P)
NetC178_2: C178.2 R192.2 U22.26(AIN_5GND)
NetC179_1: C179.1 R193.2 U22.12(AIN_6P)
NetC179_2: C179.2 R194.2 U22.13(AIN_6GND)
NetC180_1: C180.1 R195.2 U22.14(AIN_7P)
NetC180_2: C180.2 R196.2 U22.15(AIN_7GND)
NetC181_2: C181.2 R198.2 U21.3(IN+)
NetC182_2: C182.2 R200.2 U20.3(IN+)
NetC183_2: C183.2 R197.2 R198.1
NetC184_2: C184.2 R199.2 R200.1
NetC186_2: C186.2 R203.2 U20.5(IN+)
NetC187_2: C187.2 R207.2 U21.5(IN+)
NetC188_2: C188.2 R202.2 R203.1
NetC189_2: C189.2 R206.2 R207.1
NetD42_1: D42.1(K) Q5.1(D) Q5.2(D) Q5.5(D) Q5.6(D) Q5.8(D)
NetD42_2: D42.2(A) R201.1
NetQ5_3: Q5.3(G) R205.1
NetR178_1: R178.1 U22.2(~{RST}/~{PD})
NetR185_1: R185.1 U22.3(DAISY)
NetR204_2: R204.2 U23.2(A)
NetR205_2: R205.2 U23.4(Y)
NetR304_1: R304.1 U22.9(AVDD) U22.30(AVDD)
NetR305_1: R305.1 U22.34(DVDD)
NetR328_2: R328.2 U22.10(AUX_IN)
NetU22_36: U22.36(SDO) U34.2(A)

Not connected (* = marked no-connect by the designer): U22 35(DNC)*

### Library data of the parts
C152 C153 C162 C163 = 06035C104KAT2A: as C114 on sheet Page3
C154 C155 C168 C169 C181 C182 C186 C187 = C0603C470J5GACTU: as C116 on sheet Page3
C156 C159 = LMK212B7105KD-T: as C118 on sheet Page3
C157 C160 = TAJA106M010RNJ: as C119 on sheet Page3
C158 C161 = C1005X5R1A104K050BA: as C120 on sheet Page3
C164 C165 C173 C174 C183 C184 C188 C189 = 06035A101FAT2A: as C126 on sheet Page3
C166 C167 C170-C172 C178-C180 = C1608X7R1H103K080AA: as C128 on sheet Page3
C175 = GRM21BR71A106KE51L: as C137 on sheet Page3
C176 = C3225X7R1C226K250AC: as C138 on sheet Page3
C177 = C1608X7R1C105K080AC: as C139 on sheet Page3
C185 C269 = GRM188R71C104KA01D: as C147 on sheet Page3
D36-D41 D43 D44 = DESD1P0RFWQ-7: as D27-D32 on sheet Page3
D42 = LG M67K-G1J2-24-Z: as D33 on sheet Page3
J8 = SBH11-PBPC-D10-ST-BK: as J7 on sheet Page3
Q5 = CSD17571Q2: as Q4 on sheet Page3
R163-R166 R180-R183 R197-R200 R202 R203 R206 R207 = CRCW060351K0JNEA: as R118-R121 on sheet Page3
R167-R174 R304 R305 = CRCW06030000Z0EA: as R122-R129 on sheet Page3
R175-R177 R179 R184 R186-R196 = CRCW0402357RFKED: as R130-R132 on sheet Page3
R178 R185 = RC0603FR-0747KL: as R133 on sheet Page3
R201 R205 = CRCW0603300RJNEA: as R156 on sheet Page3
R204 = RMCF0603ZT0R00: as R159 on sheet Page3
R324-R328 = CRCW04020000Z0ED: as R319-R323 on sheet Page3
U20 U21 = OPA4197IPWR: as U16 on sheet Page3
U22 = ADS8688IDBT: as U18 on sheet Page3
U23 U34 = SN74LVC1G17DCKR: as U19 on sheet Page3

## Sheet Page5.SchDoc
size 431 x 279 mm; Date: Not shown in title block; ApprovedBy: Not shown in title block; CheckedBy: Not shown in title block; Author: Not shown in title block; CompanyName: Not shown in title block; Engineer: Not shown in title block; Organization: Not shown in title block; Address1: Not shown in title block; Address2: Not shown in title block; Address3: Not shown in title block; Address4: Not shown in title block; DocumentNumber: 1; Revision: Use project parameter SCH_Rev; SheetNumber: 2; SheetTotal: 3; PageSetup: Record=PageOptions¦CenterHorizontal=True¦CenterVertical=True¦PrintScale=0.62¦XCorrection=1.00¦YCorrection=1.00¦PrintKind=0¦BorderSize=5000000¦LeftOffset=0¦BottomOffset=0¦Orientation=2¦PaperLength=1000¦PaperWidth=1000¦Scale=100¦PaperSource=15¦PrintQuality=600¦MediaType=1¦DitherType=10¦PrintScaleMode=1¦PaperKind=Letter
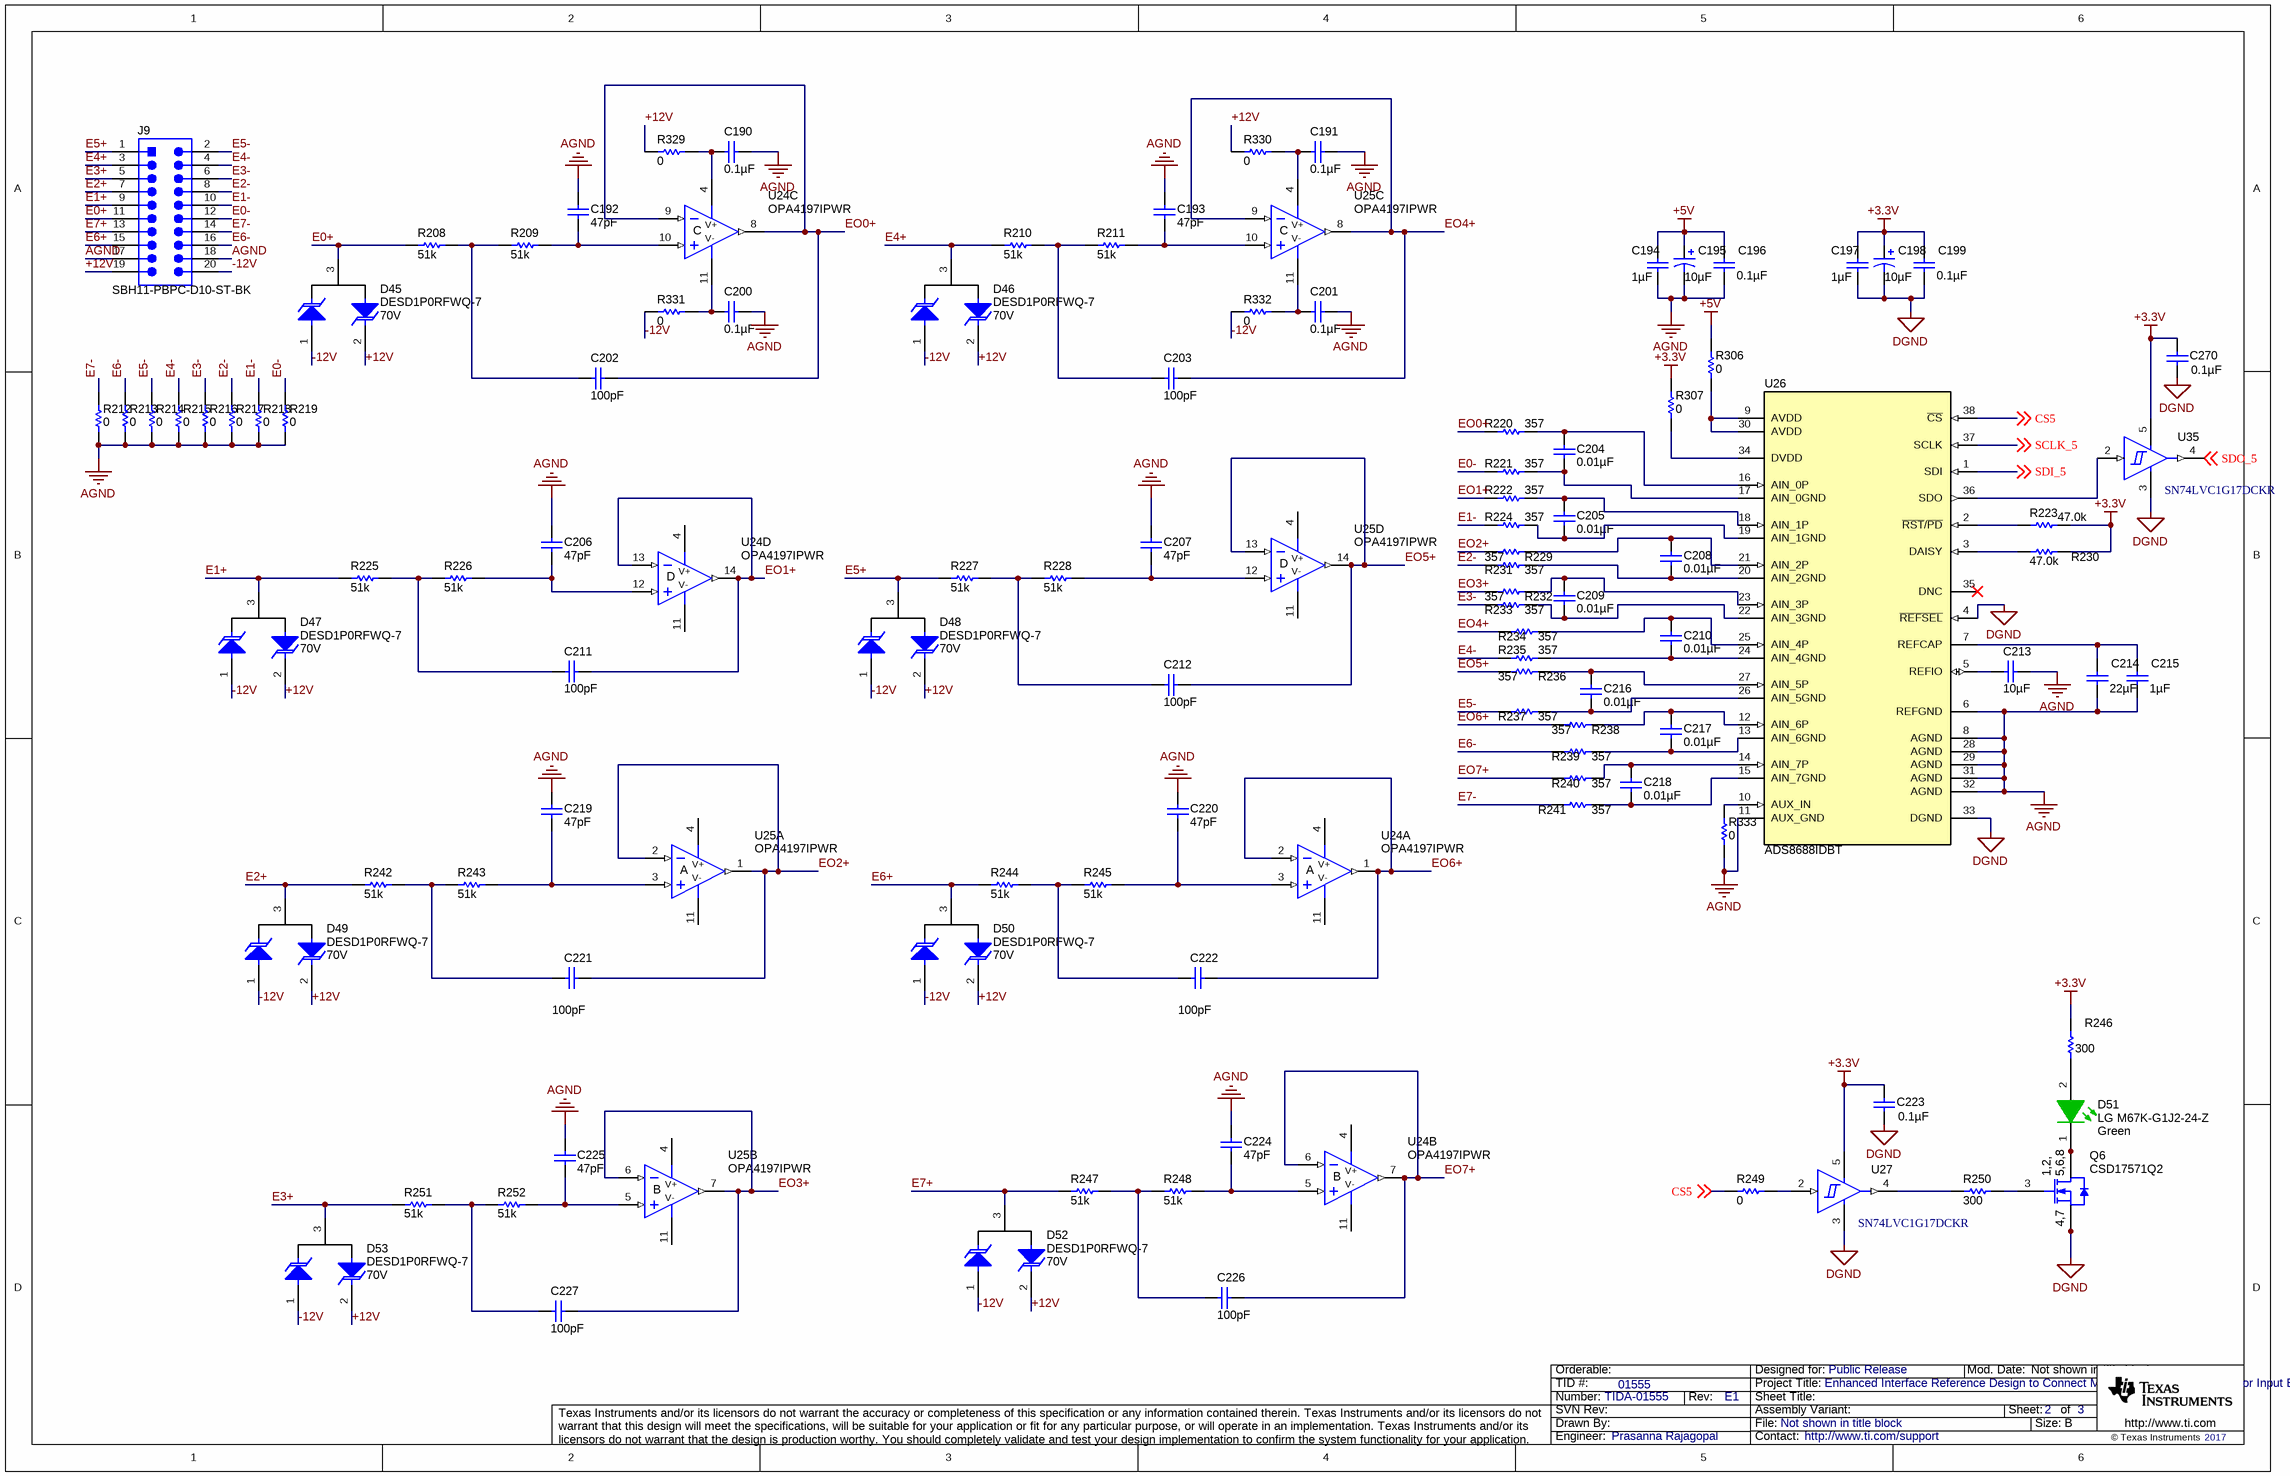
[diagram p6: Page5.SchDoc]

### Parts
C190  ValueDisplayed: 0.1µF  [0603]  (hidden comment: 06035C104KAT2A)
C191  ValueDisplayed: 0.1µF  [0603]  (hidden comment: 06035C104KAT2A)
C192  ValueDisplayed: 47pF  [0603]  (hidden comment: C0603C470J5GACTU)
C193  ValueDisplayed: 47pF  [0603]  (hidden comment: C0603C470J5GACTU)
C194  ValueDisplayed: 1µF  [0805_HV]  (hidden comment: LMK212B7105KD-T)
C195  ValueDisplayed: 10µF  [3216-18]  (hidden comment: TAJA106M010RNJ)
C196  ValueDisplayed: 0.1µF  [0402]  (hidden comment: C1005X5R1A104K050BA)
C197  ValueDisplayed: 1µF  [0805_HV]  (hidden comment: LMK212B7105KD-T)
C198  ValueDisplayed: 10µF  [3216-18]  (hidden comment: TAJA106M010RNJ)
C199  ValueDisplayed: 0.1µF  [0402]  (hidden comment: C1005X5R1A104K050BA)
C200  ValueDisplayed: 0.1µF  [0603]  (hidden comment: 06035C104KAT2A)
C201  ValueDisplayed: 0.1µF  [0603]  (hidden comment: 06035C104KAT2A)
C202  ValueDisplayed: 100pF  [0603]  (hidden comment: 06035A101FAT2A)
C203  ValueDisplayed: 100pF  [0603]  (hidden comment: 06035A101FAT2A)
C204  ValueDisplayed: 0.01µF  [0603]  (hidden comment: C1608X7R1H103K080AA)
C205  ValueDisplayed: 0.01µF  [0603]  (hidden comment: C1608X7R1H103K080AA)
C206  ValueDisplayed: 47pF  [0603]  (hidden comment: C0603C470J5GACTU)
C207  ValueDisplayed: 47pF  [0603]  (hidden comment: C0603C470J5GACTU)
C208  ValueDisplayed: 0.01µF  [0603]  (hidden comment: C1608X7R1H103K080AA)
C209  ValueDisplayed: 0.01µF  [0603]  (hidden comment: C1608X7R1H103K080AA)
C210  ValueDisplayed: 0.01µF  [0603]  (hidden comment: C1608X7R1H103K080AA)
C211  ValueDisplayed: 100pF  [0603]  (hidden comment: 06035A101FAT2A)
C212  ValueDisplayed: 100pF  [0603]  (hidden comment: 06035A101FAT2A)
C213  ValueDisplayed: 10µF  [0805_HV]  (hidden comment: GRM21BR71A106KE51L)
C214  ValueDisplayed: 22µF  [1210_280]  (hidden comment: C3225X7R1C226K250AC)
C215  ValueDisplayed: 1µF  [0603]  (hidden comment: C1608X7R1C105K080AC)
C216  ValueDisplayed: 0.01µF  [0603]  (hidden comment: C1608X7R1H103K080AA)
C217  ValueDisplayed: 0.01µF  [0603]  (hidden comment: C1608X7R1H103K080AA)
C218  ValueDisplayed: 0.01µF  [0603]  (hidden comment: C1608X7R1H103K080AA)
C219  ValueDisplayed: 47pF  [0603]  (hidden comment: C0603C470J5GACTU)
C220  ValueDisplayed: 47pF  [0603]  (hidden comment: C0603C470J5GACTU)
C221  ValueDisplayed: 100pF  [0603]  (hidden comment: 06035A101FAT2A)
C222  ValueDisplayed: 100pF  [0603]  (hidden comment: 06035A101FAT2A)
C223  ValueDisplayed: 0.1µF  [0603]  (hidden comment: GRM188R71C104KA01D)
C224  ValueDisplayed: 47pF  [0603]  (hidden comment: C0603C470J5GACTU)
C225  ValueDisplayed: 47pF  [0603]  (hidden comment: C0603C470J5GACTU)
C226  ValueDisplayed: 100pF  [0603]  (hidden comment: 06035A101FAT2A)
C227  ValueDisplayed: 100pF  [0603]  (hidden comment: 06035A101FAT2A)
C270  ValueDisplayed: 0.1µF  [0603]  (hidden comment: GRM188R71C104KA01D)
D45  DESD1P0RFWQ-7  value 70V  [SOT-323]
D46  DESD1P0RFWQ-7  value 70V  [SOT-323]
D47  DESD1P0RFWQ-7  value 70V  [SOT-323]
D48  DESD1P0RFWQ-7  value 70V  [SOT-323]
D49  DESD1P0RFWQ-7  value 70V  [SOT-323]
D50  DESD1P0RFWQ-7  value 70V  [SOT-323]
D51  LG M67K-G1J2-24-Z  value Green  [LG_M67K_Green]
D52  DESD1P0RFWQ-7  value 70V  [SOT-323]
D53  DESD1P0RFWQ-7  value 70V  [SOT-323]
J9  SBH11-PBPC-D10-ST-BK  [Sullins_SBH11-xxxC-D10-ST]
Q6  CSD17571Q2  [DQK0006C]
R208  ValueDisplayed: 51k  [0603]  (hidden comment: CRCW060351K0JNEA)
R209  ValueDisplayed: 51k  [0603]  (hidden comment: CRCW060351K0JNEA)
R210  ValueDisplayed: 51k  [0603]  (hidden comment: CRCW060351K0JNEA)
R211  ValueDisplayed: 51k  [0603]  (hidden comment: CRCW060351K0JNEA)
R212  ValueDisplayed: 0  [0603]  (hidden comment: CRCW06030000Z0EA)
R213  ValueDisplayed: 0  [0603]  (hidden comment: CRCW06030000Z0EA)
R214  ValueDisplayed: 0  [0603]  (hidden comment: CRCW06030000Z0EA)
R215  ValueDisplayed: 0  [0603]  (hidden comment: CRCW06030000Z0EA)
R216  ValueDisplayed: 0  [0603]  (hidden comment: CRCW06030000Z0EA)
R217  ValueDisplayed: 0  [0603]  (hidden comment: CRCW06030000Z0EA)
R218  ValueDisplayed: 0  [0603]  (hidden comment: CRCW06030000Z0EA)
R219  ValueDisplayed: 0  [0603]  (hidden comment: CRCW06030000Z0EA)
R220  ValueDisplayed: 357  [0402]  (hidden comment: CRCW0402357RFKED)
R221  ValueDisplayed: 357  [0402]  (hidden comment: CRCW0402357RFKED)
R222  ValueDisplayed: 357  [0402]  (hidden comment: CRCW0402357RFKED)
R223  ValueDisplayed: 47.0k  [0603]  (hidden comment: RC0603FR-0747KL)
R224  ValueDisplayed: 357  [0402]  (hidden comment: CRCW0402357RFKED)
R225  ValueDisplayed: 51k  [0603]  (hidden comment: CRCW060351K0JNEA)
R226  ValueDisplayed: 51k  [0603]  (hidden comment: CRCW060351K0JNEA)
R227  ValueDisplayed: 51k  [0603]  (hidden comment: CRCW060351K0JNEA)
R228  ValueDisplayed: 51k  [0603]  (hidden comment: CRCW060351K0JNEA)
R229  ValueDisplayed: 357  [0402]  (hidden comment: CRCW0402357RFKED)
R230  ValueDisplayed: 47.0k  [0603]  (hidden comment: RC0603FR-0747KL)
R231  ValueDisplayed: 357  [0402]  (hidden comment: CRCW0402357RFKED)
R232  ValueDisplayed: 357  [0402]  (hidden comment: CRCW0402357RFKED)
R233  ValueDisplayed: 357  [0402]  (hidden comment: CRCW0402357RFKED)
R234  ValueDisplayed: 357  [0402]  (hidden comment: CRCW0402357RFKED)
R235  ValueDisplayed: 357  [0402]  (hidden comment: CRCW0402357RFKED)
R236  ValueDisplayed: 357  [0402]  (hidden comment: CRCW0402357RFKED)
R237  ValueDisplayed: 357  [0402]  (hidden comment: CRCW0402357RFKED)
R238  ValueDisplayed: 357  [0402]  (hidden comment: CRCW0402357RFKED)
R239  ValueDisplayed: 357  [0402]  (hidden comment: CRCW0402357RFKED)
R240  ValueDisplayed: 357  [0402]  (hidden comment: CRCW0402357RFKED)
R241  ValueDisplayed: 357  [0402]  (hidden comment: CRCW0402357RFKED)
R242  ValueDisplayed: 51k  [0603]  (hidden comment: CRCW060351K0JNEA)
R243  ValueDisplayed: 51k  [0603]  (hidden comment: CRCW060351K0JNEA)
R244  ValueDisplayed: 51k  [0603]  (hidden comment: CRCW060351K0JNEA)
R245  ValueDisplayed: 51k  [0603]  (hidden comment: CRCW060351K0JNEA)
R246  ValueDisplayed: 300  [0603]  (hidden comment: CRCW0603300RJNEA)
R247  ValueDisplayed: 51k  [0603]  (hidden comment: CRCW060351K0JNEA)
R248  ValueDisplayed: 51k  [0603]  (hidden comment: CRCW060351K0JNEA)
R249  ValueDisplayed: 0  [0603]  (hidden comment: RMCF0603ZT0R00)
R250  ValueDisplayed: 300  [0603]  (hidden comment: CRCW0603300RJNEA)
R251  ValueDisplayed: 51k  [0603]  (hidden comment: CRCW060351K0JNEA)
R252  ValueDisplayed: 51k  [0603]  (hidden comment: CRCW060351K0JNEA)
R306  ValueDisplayed: 0  [0603]  (hidden comment: CRCW06030000Z0EA)
R307  ValueDisplayed: 0  [0603]  (hidden comment: CRCW06030000Z0EA)
R329  ValueDisplayed: 0  [0402]  (hidden comment: CRCW04020000Z0ED)
R330  ValueDisplayed: 0  [0402]  (hidden comment: CRCW04020000Z0ED)
R331  ValueDisplayed: 0  [0402]  (hidden comment: CRCW04020000Z0ED)
R332  ValueDisplayed: 0  [0402]  (hidden comment: CRCW04020000Z0ED)
R333  ValueDisplayed: 0  [0402]  (hidden comment: CRCW04020000Z0ED)
U24  OPA4197IPWR  [PW0014A_N]  (parts A,B,C,D of 4)
U25  OPA4197IPWR  [PW0014A_N]  (parts A,B,C,D of 4)
U26  ADS8688IDBT  [DBT0038A_N]
U27  SN74LVC1G17DCKR  [DCK0005A_N]
U35  SN74LVC1G17DCKR  [DCK0005A_N]

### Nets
+3.3V: C197.1 C198.1(+) C199.1 C223.1 C270.1 R223.2 R230.2 R246.2 R307.2 U27.5(VCC) U35.5(VCC)
+5V: C194.1 C195.1(+) C196.1 R306.2
+12V: D45.2(C) D46.2(C) D47.2(C) D48.2(C) D49.2(C) D50.2(C) D52.2(C) D53.2(C) J9.19 R329.1 R330.1
-12V: D45.1(A) D46.1(A) D47.1(A) D48.1(A) D49.1(A) D50.1(A) D52.1(A) D53.1(A) J9.20 R331.1 R332.1
AGND: C190.1 C191.1 C192.1 C193.1 C194.2 C195.2(-) C196.2 C200.1 C201.1 C206.1 C207.1 C213.2 C214.2 C215.2 C219.1 C220.1 C224.1 C225.1 J9.17 J9.18 R212.1 R213.1 R214.1 R215.1 R216.1 R217.1 R218.1 R219.1 R333.1 U26.6(REFGND) U26.8(AGND) U26.11(AUX_GND) U26.28(AGND) U26.29(AGND) U26.31(AGND) U26.32(AGND)
DGND: C197.2 C198.2(-) C199.2 C223.2 C270.2 Q6.4(S) Q6.7(S) U26.4(~{REFSEL}) U26.33(DGND) U27.3(GND) U35.3(GND)
CS5: R249.1 U26.38(~{CS}) ; off-sheet CS5
E0+: D45.3(C) J9.11 R208.1
E0-: J9.12 R219.2 R221.1
E1+: D47.3(C) J9.9 R225.1
E1-: J9.10 R218.2 R224.1
E2+: D49.3(C) J9.7 R242.1
E2-: J9.8 R217.2 R231.1
E3+: D53.3(C) J9.5 R251.1
E3-: J9.6 R216.2 R233.1
E4+: D46.3(C) J9.3 R210.1
E4-: J9.4 R215.2 R235.1
E5+: D48.3(C) J9.1 R227.1
E5-: J9.2 R214.2 R237.1
E6+: D50.3(C) J9.15 R244.1
E6-: J9.16 R213.2 R239.1
E7+: D52.3(C) J9.13 R247.1
E7-: J9.14 R212.2 R241.1
EO0+: C202.1 R220.1 U24.8(OUT) U24.9(IN-)
EO1+: C211.1 R222.1 U24.13(IN-) U24.14(OUT)
EO2+: C221.1 R229.1 U25.1(OUT) U25.2(IN-)
EO3+: C227.1 R232.1 U25.6(IN-) U25.7(OUT)
EO4+: C203.1 R234.1 U25.8(OUT) U25.9(IN-)
EO5+: C212.1 R236.1 U25.13(IN-) U25.14(OUT)
EO6+: C222.1 R238.1 U24.1(OUT) U24.2(IN-)
EO7+: C226.1 R240.1 U24.6(IN-) U24.7(OUT)
SCLK_5: U26.37(SCLK) ; off-sheet SCLK_5
SDI_5: U26.1(SDI) ; off-sheet SDI_5
SDO_5: U35.4(Y) ; off-sheet SDO_5
NetC190_2: C190.2 R329.2 U24.4(V+)
NetC191_2: C191.2 R330.2 U25.4(V+)
NetC192_2: C192.2 R209.2 U24.10(IN+)
NetC193_2: C193.2 R211.2 U25.10(IN+)
NetC200_2: C200.2 R331.2 U24.11(V-)
NetC201_2: C201.2 R332.2 U25.11(V-)
NetC202_2: C202.2 R208.2 R209.1
NetC203_2: C203.2 R210.2 R211.1
NetC204_1: C204.1 R220.2 U26.16(AIN_0P)
NetC204_2: C204.2 R221.2 U26.17(AIN_0GND)
NetC205_1: C205.1 R222.2 U26.18(AIN_1P)
NetC205_2: C205.2 R224.2 U26.19(AIN_1GND)
NetC206_2: C206.2 R226.2 U24.12(IN+)
NetC207_2: C207.2 R228.2 U25.12(IN+)
NetC208_1: C208.1 R229.2 U26.21(AIN_2P)
NetC208_2: C208.2 R231.2 U26.20(AIN_2GND)
NetC209_1: C209.1 R232.2 U26.23(AIN_3P)
NetC209_2: C209.2 R233.2 U26.22(AIN_3GND)
NetC210_1: C210.1 R234.2 U26.25(AIN_4P)
NetC210_2: C210.2 R235.2 U26.24(AIN_4GND)
NetC211_2: C211.2 R225.2 R226.1
NetC212_2: C212.2 R227.2 R228.1
NetC213_1: C213.1 U26.5(REFIO)
NetC214_1: C214.1 C215.1 U26.7(REFCAP)
NetC216_1: C216.1 R236.2 U26.27(AIN_5P)
NetC216_2: C216.2 R237.2 U26.26(AIN_5GND)
NetC217_1: C217.1 R238.2 U26.12(AIN_6P)
NetC217_2: C217.2 R239.2 U26.13(AIN_6GND)
NetC218_1: C218.1 R240.2 U26.14(AIN_7P)
NetC218_2: C218.2 R241.2 U26.15(AIN_7GND)
NetC219_2: C219.2 R243.2 U25.3(IN+)
NetC220_2: C220.2 R245.2 U24.3(IN+)
NetC221_2: C221.2 R242.2 R243.1
NetC222_2: C222.2 R244.2 R245.1
NetC224_2: C224.2 R248.2 U24.5(IN+)
NetC225_2: C225.2 R252.2 U25.5(IN+)
NetC226_2: C226.2 R247.2 R248.1
NetC227_2: C227.2 R251.2 R252.1
NetD51_1: D51.1(K) Q6.1(D) Q6.2(D) Q6.5(D) Q6.6(D) Q6.8(D)
NetD51_2: D51.2(A) R246.1
NetQ6_3: Q6.3(G) R250.1
NetR223_1: R223.1 U26.2(~{RST}/~{PD})
NetR230_1: R230.1 U26.3(DAISY)
NetR249_2: R249.2 U27.2(A)
NetR250_2: R250.2 U27.4(Y)
NetR306_1: R306.1 U26.9(AVDD) U26.30(AVDD)
NetR307_1: R307.1 U26.34(DVDD)
NetR333_2: R333.2 U26.10(AUX_IN)
NetU26_36: U26.36(SDO) U35.2(A)

Not connected (* = marked no-connect by the designer): U26 35(DNC)*

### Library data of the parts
C190 C191 C200 C201 = 06035C104KAT2A: as C114 on sheet Page3
C192 C193 C206 C207 C219 C220 C224 C225 = C0603C470J5GACTU: as C116 on sheet Page3
C194 C197 = LMK212B7105KD-T: as C118 on sheet Page3
C195 C198 = TAJA106M010RNJ: as C119 on sheet Page3
C196 C199 = C1005X5R1A104K050BA: as C120 on sheet Page3
C202 C203 C211 C212 C221 C222 C226 C227 = 06035A101FAT2A: as C126 on sheet Page3
C204 C205 C208-C210 C216-C218 = C1608X7R1H103K080AA: as C128 on sheet Page3
C213 = GRM21BR71A106KE51L: as C137 on sheet Page3
C214 = C3225X7R1C226K250AC: as C138 on sheet Page3
C215 = C1608X7R1C105K080AC: as C139 on sheet Page3
C223 C270 = GRM188R71C104KA01D: as C147 on sheet Page3
D45-D50 D52 D53 = DESD1P0RFWQ-7: as D27-D32 on sheet Page3
D51 = LG M67K-G1J2-24-Z: as D33 on sheet Page3
J9 = SBH11-PBPC-D10-ST-BK: as J7 on sheet Page3
Q6 = CSD17571Q2: as Q4 on sheet Page3
R208-R211 R225-R228 R242-R245 R247 R248 R251 R252 = CRCW060351K0JNEA: as R118-R121 on sheet Page3
R212-R219 R306 R307 = CRCW06030000Z0EA: as R122-R129 on sheet Page3
R220-R222 R224 R229 R231-R241 = CRCW0402357RFKED: as R130-R132 on sheet Page3
R223 R230 = RC0603FR-0747KL: as R133 on sheet Page3
R246 R250 = CRCW0603300RJNEA: as R156 on sheet Page3
R249 = RMCF0603ZT0R00: as R159 on sheet Page3
R329-R333 = CRCW04020000Z0ED: as R319-R323 on sheet Page3
U24 U25 = OPA4197IPWR: as U16 on sheet Page3
U26 = ADS8688IDBT: as U18 on sheet Page3
U27 U35 = SN74LVC1G17DCKR: as U19 on sheet Page3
